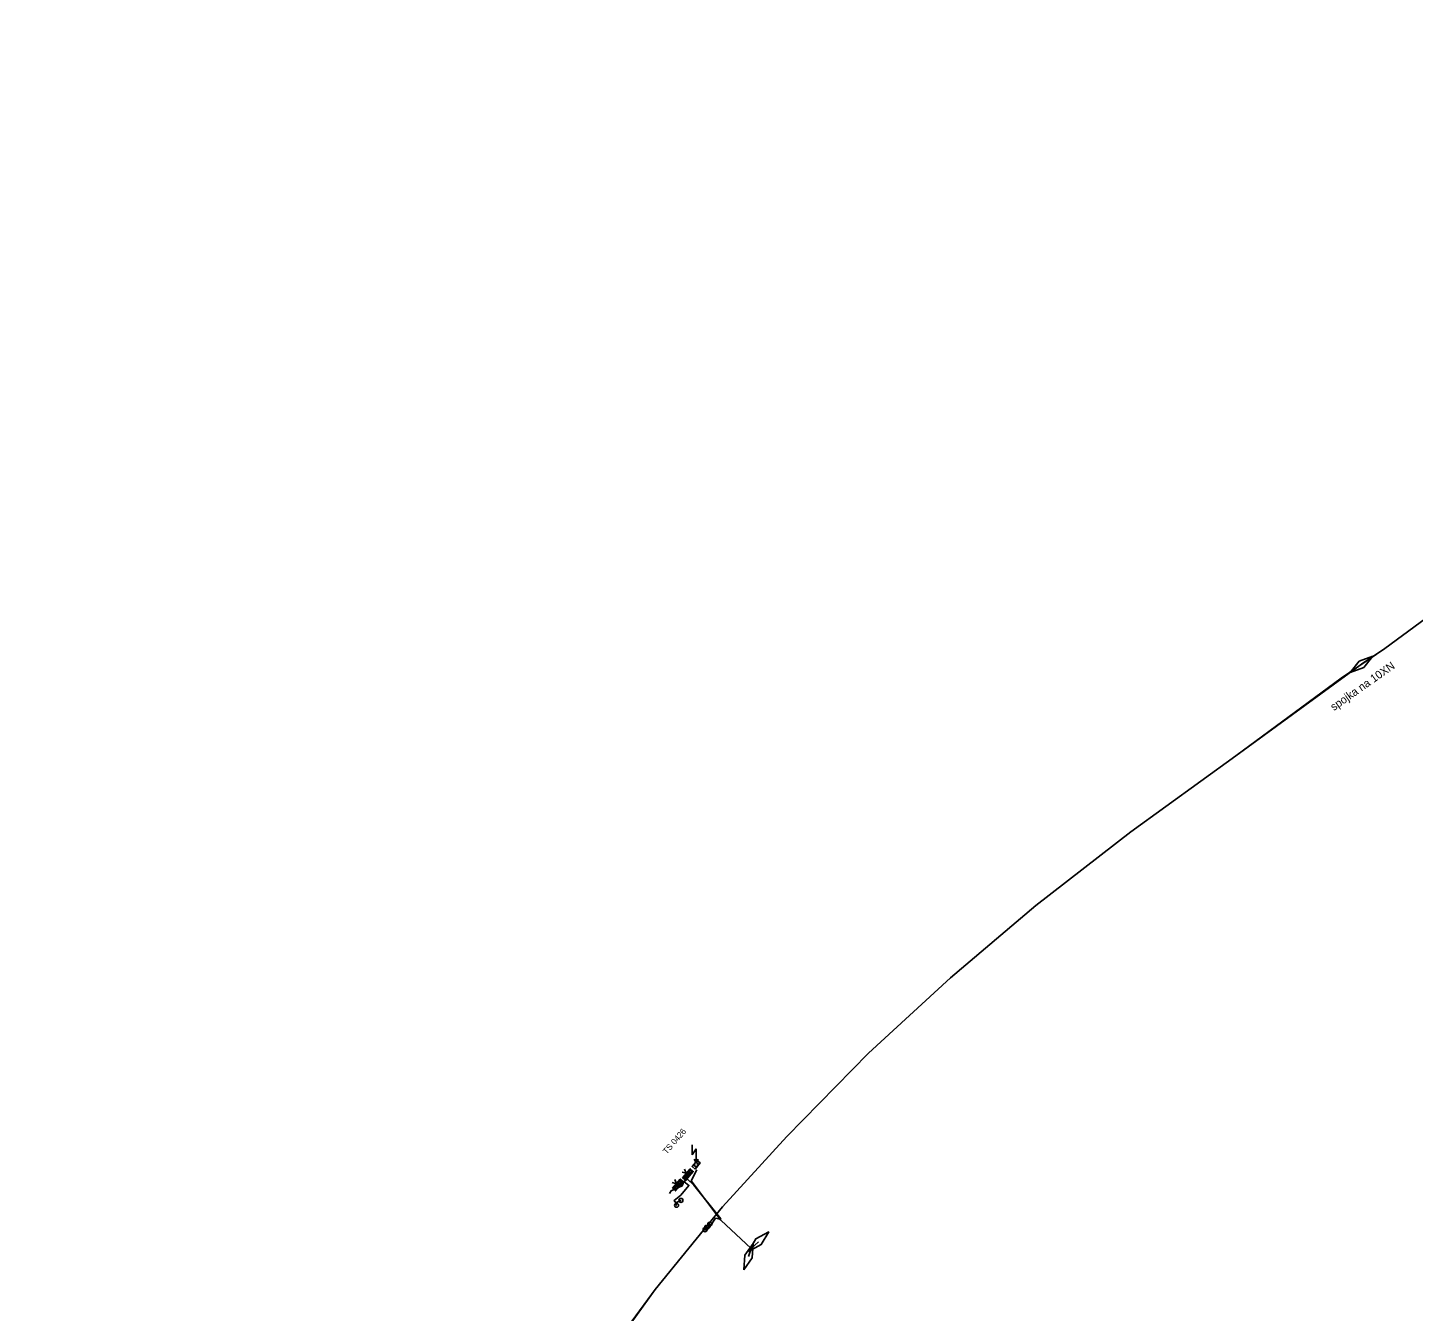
# Model space of a CAD drawing. Extents: x -748507 to -687366, y -1057342 to -1024924.
# Drawn here: x -746523.6 to -746177.3, y -1032508.7 to -1032188 of the extents above; entities that cross this region are included whole.
import ezdxf

# ---------------------------------------------------------------- set-up
doc = ezdxf.new("R2010")
doc.units = 0
for name, color, linetype in [('6kV - SŽDC', 7, 'Continuous'), ('DK + TKK - SŽDC', 7, 'Continuous'), ('TK+DOK_Pha Holešovice - Kralupy', 7, 'Continuous')]:
    doc.layers.add(name, color=color, linetype=linetype)

msp = doc.modelspace()

# ---------------------------------------------------------------- linework, layer by layer
at = {"layer": '6kV - SŽDC'}
for p, q in [((-746357.55, -1032467.04), (-746357.55, -1032469.54)), ((-746357.55, -1032469.54), (-746356.55, -1032468.04)), ((-746356.55, -1032468.04), (-746356.55, -1032471.54)), ((-746357.05, -1032470.64), (-746356.55, -1032471.54)), ((-746356.6, -1032472.04), (-746356.5, -1032472.04)), ((-746356.55, -1032471.54), (-746356.05, -1032470.64))]:
    msp.add_line(p, q, dxfattribs=at)
for points in [[(-746342.77, -1032493.01), (-746350.37, -1032485.89), (-746357.77, -1032476.11), (-746356.35, -1032473.34)], [(-746356.83, -1032473.12), (-746357.58, -1032472.46), (-746356.27, -1032470.96), (-746355.52, -1032471.61), (-746356.83, -1032473.12)], [(-746343.48, -1032493.69), (-746341.64, -1032490.55), (-746338.42, -1032488.85), (-746340.26, -1032491.99), (-746343.48, -1032493.69)], [(-746344.61, -1032498.3), (-746344.4, -1032494.66), (-746342.31, -1032491.69), (-746342.52, -1032495.32), (-746344.61, -1032498.3)], [(-746343.46, -1032494.99), (-746342.77, -1032493.01), (-746340.95, -1032491.27)]]:
    msp.add_lwpolyline(points, dxfattribs=at)
msp.add_circle((-746356.55, -1032472.04), 0.5, dxfattribs=at)
at = {"layer": 'DK + TKK - SŽDC'}
for p, q in [((-746358.35, -1032474.96), (-746358.45, -1032473.55)), ((-746358, -1032474.56), (-746358.11, -1032473.15)), ((-746357.65, -1032474.15), (-746357.72, -1032473.31)), ((-746357.31, -1032473.75), (-746357.32, -1032473.65)), ((-746361.5, -1032478.35), (-746361.61, -1032476.95)), ((-746361.16, -1032477.95), (-746361.27, -1032476.54)), ((-746360.81, -1032477.55), (-746360.93, -1032476.14)), ((-746360.47, -1032477.14), (-746360.58, -1032475.73)), ((-746360.13, -1032476.74), (-746360.2, -1032475.89)), ((-746359.81, -1032475.46), (-746359.83, -1032475.16)), ((-746359.78, -1032476.33), (-746359.79, -1032476.23)), ((-746359.41, -1032475.81), (-746359.49, -1032474.75)), ((-746359.04, -1032475.76), (-746359.14, -1032474.35)), ((-746358.69, -1032475.36), (-746358.8, -1032473.95)), ((-746362.28, -1032478.06), (-746362.3, -1032477.75)), ((-746361.87, -1032478.4), (-746361.96, -1032477.35)), ((-746361.49, -1032482.17), (-746361.39, -1032482.17)), ((-746360.4, -1032480.96), (-746360.3, -1032480.96)), ((-746353.2, -1032486.91), (-746353.1, -1032486.91)), ((-746354.37, -1032488.28), (-746354.27, -1032488.28)), ((-746353.96, -1032487.7), (-746353.86, -1032487.7))]:
    msp.add_line(p, q, dxfattribs=at)
for points in [[(-746333.91, -1032464.99), (-746313.5, -1032444.19), (-746292.99, -1032425.34), (-746271.69, -1032407.27), (-746247.89, -1032388.89), (-746221.69, -1032369.89), (-746195.34, -1032350.49), (-746184.44, -1032343.07), (-746166.78, -1032330.14)], [(-746521.39, -1033026.05), (-746523.51, -1032995.09), (-746523.58, -1032962.87), (-746521.78, -1032933.46), (-746519.19, -1032905.33), (-746514.34, -1032878.13), (-746506.47, -1032843.03), (-746499.79, -1032816.87), (-746489.29, -1032777.89), (-746483.48, -1032757.14), (-746477.1, -1032733.55), (-746471.34, -1032713.91), (-746465.19, -1032692.35), (-746455.16, -1032662.59), (-746444.56, -1032635.79), (-746432.32, -1032608.9), (-746419.88, -1032584.89), (-746404.89, -1032558.38), (-746384.96, -1032527.92), (-746366.79, -1032503.18), (-746349.94, -1032482.56), (-746333.91, -1032464.99)], [(-746360.08, -1032473.91), (-746359, -1032474.18), (-746359.43, -1032473.15)], [(-746359.98, -1032475.32), (-746358.02, -1032473.05), (-746357.26, -1032473.7), (-746359.22, -1032475.97), (-746359.98, -1032475.32)], [(-746359.66, -1032476.2), (-746360.06, -1032477.35), (-746362.79, -1032478.59), (-746363.19, -1032479.21)], [(-746362.56, -1032476.51), (-746361.47, -1032476.78), (-746361.91, -1032475.75)], [(-746362.44, -1032477.92), (-746360.5, -1032475.63), (-746359.74, -1032476.28), (-746361.68, -1032478.57), (-746362.44, -1032477.92)], [(-746353.29, -1032487.82), (-746351.67, -1032485.42), (-746350.54, -1032485.62), (-746350.4, -1032485.54), (-746357.1, -1032477.12), (-746358.71, -1032475.63), (-746359.66, -1032476.2), (-746358.36, -1032477.21), (-746360.41, -1032479.62), (-746362, -1032480.95), (-746361.61, -1032481.57), (-746361.44, -1032482.17)], [(-746361.61, -1032481.57), (-746360.35, -1032480.96)], [(-746353.29, -1032487.82), (-746353.15, -1032486.91)], [(-746354.32, -1032488.28), (-746353.29, -1032487.82), (-746353.91, -1032487.7)]]:
    msp.add_lwpolyline(points, dxfattribs=at)
for points in [[(-746359.98, -1032475.32), (-746358.02, -1032473.05), (-746357.26, -1032473.7), (-746359.22, -1032475.97)], [(-746362.44, -1032477.92), (-746360.5, -1032475.63), (-746359.74, -1032476.28), (-746361.68, -1032478.57)]]:
    msp.add_lwpolyline(points, close=True, dxfattribs=at)
for centre in [(-746360.35, -1032480.96), (-746361.44, -1032482.17), (-746353.91, -1032487.7), (-746353.15, -1032486.91), (-746354.32, -1032488.28)]:
    msp.add_circle(centre, 0.5, dxfattribs=at)
at = {"layer": 'TK+DOK_Pha Holešovice - Kralupy'}
for points in [[(-746190.27, -1032347.04), (-746184.44, -1032343.07), (-746166.78, -1032330.14), (-746150.46, -1032318.03), (-746124.36, -1032299.42), (-746096.9, -1032279.78), (-746067.06, -1032258.72), (-746039.24, -1032239.94), (-746010.01, -1032222.02), (-745980.93, -1032206.37), (-745942.86, -1032188.03)], [(-746388.45, -1032533.25), (-746366.79, -1032503.18), (-746349.94, -1032482.56), (-746333.91, -1032464.99), (-746313.5, -1032444.19), (-746292.99, -1032425.34), (-746271.69, -1032407.27), (-746247.89, -1032388.89), (-746221.69, -1032369.89), (-746190.27, -1032347.04), (-746184.44, -1032343.07), (-746166.78, -1032330.14)], [(-746193.14, -1032349.06), (-746190.85, -1032346.22), (-746187.41, -1032345.03), (-746189.7, -1032347.86), (-746193.14, -1032349.06)], [(-746388.45, -1032533.25), (-746366.79, -1032503.18), (-746349.94, -1032482.56), (-746333.91, -1032464.99), (-746313.5, -1032444.19), (-746292.99, -1032425.34), (-746271.69, -1032407.27), (-746247.89, -1032388.89), (-746221.69, -1032369.89), (-746190.27, -1032347.04)]]:
    msp.add_lwpolyline(points, dxfattribs=at)

# ---------------------------------------------------------------- texts
at = {"layer": '6kV - SŽDC'}
msp.add_text('TS 0426', height=1.5, rotation=48.8864, dxfattribs=at).set_placement((-746363.91, -1032469.53))
at = {"layer": 'TK+DOK_Pha Holešovice - Kralupy'}
msp.add_text('spojka na 10XN', height=2, rotation=35.1404, dxfattribs=at).set_placement((-746197.19, -1032358.74))

doc.saveas('drawing.dxf')
